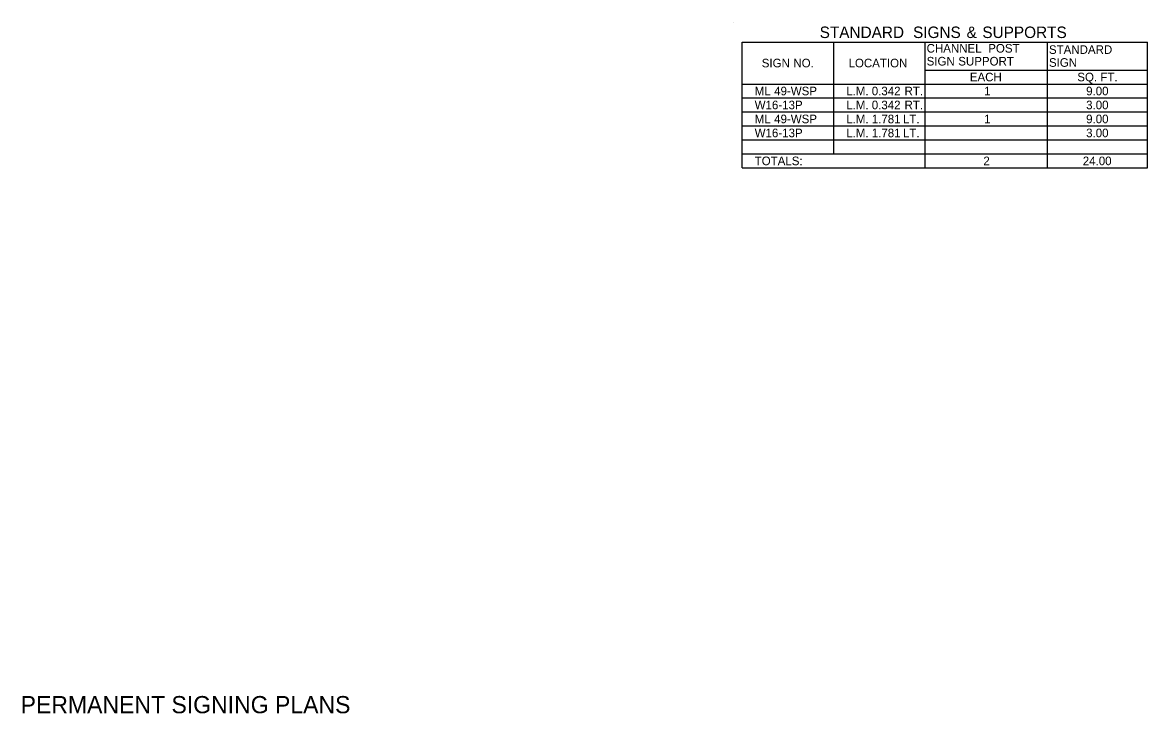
# Model space of a CAD drawing. Extents: x 229 to 4210, y 35 to 1715.
# Drawn here: x 3425 to 4210, y 35 to 517 of the extents above; entities that cross this region are included whole.
import ezdxf

# ---------------------------------------------------------------- set-up
doc = ezdxf.new("R2010")
doc.units = 0
for name, color, linetype in [('B_Steel', 7, 'Continuous'), ('B_Steel Hidden', 7, 'Continuous'), ('Default', 7, 'Continuous')]:
    doc.layers.add(name, color=color, linetype=linetype)

msp = doc.modelspace()

# ---------------------------------------------------------------- linework, layer by layer
at = {"layer": 'B_Steel Hidden'}
msp.add_line((3920.99, 516.95), (3920.99, 516.95), dxfattribs=at)
at = {"layer": 'Default'}
for p, q in [((3926.84, 503.3), (4209.59, 503.3)), ((3926.84, 415.55), (3926.84, 503.3)), ((3926.84, 415.55), (3926.84, 503.3)), ((3990.7, 425.3), (3990.7, 503.3)), ((4054.56, 415.55), (4054.56, 503.3)), ((4139.87, 483.8), (4139.87, 503.3)), ((4139.87, 415.55), (4139.87, 503.3)), ((4209.59, 415.55), (4209.59, 503.3)), ((4054.56, 483.8), (4209.59, 483.8)), ((4054.56, 483.8), (4209.59, 483.8)), ((3926.84, 474.05), (4209.59, 474.05)), ((3990.7, 425.3), (3990.7, 474.05)), ((4054.56, 474.05), (4209.59, 474.05)), ((4054.56, 425.3), (4054.56, 474.05)), ((4139.87, 425.3), (4139.87, 474.05)), ((3926.84, 464.3), (4209.59, 464.3)), ((3926.84, 454.55), (4209.59, 454.55)), ((3926.84, 444.8), (4209.59, 444.8)), ((3926.84, 435.05), (4209.59, 435.05)), ((3926.84, 425.3), (4209.59, 425.3)), ((4209.59, 415.55), (4209.59, 425.3)), ((3926.84, 415.55), (4209.59, 415.55))]:
    msp.add_line(p, q, dxfattribs=at)

# ---------------------------------------------------------------- texts
at = {"layer": 'B_Steel'}
msp.add_text('PERMANENT SIGNING PLANS', height=12, rotation=360, dxfattribs=at).set_placement((3423.61, 35.16))
at = {"layer": 'Default'}
for s, height, p in [('STANDARD', 8, (3980.93, 506.12)), (' SIGNS', 8, (4043.1, 506.12)), (' &', 8, (4080.44, 506.12)), (' SUPPORTS', 8, (4091.44, 506.12)), ('CHANNEL', 6, (4055.54, 495.95)), (' POST', 6, (4096.27, 495.95)), ('STANDARD', 6, (4140.85, 495.05)), ('SIGN', 6, (3940.53, 485.67)), (' NO.', 6, (3960.35, 485.67)), ('LOCATION', 6, (4001.08, 485.67)), ('SIGN', 6, (4055.54, 486.95)), (' SUPPORT', 6, (4075.36, 486.95)), ('SIGN', 6, (4140.85, 486.05)), ('EACH', 6, (4085.66, 475.92)), ('SQ.', 6, (4160.63, 475.92)), (' FT.', 6, (4174.5, 475.92)), ('ML', 6, (3935.61, 466.17)), (' 49-WSP', 6, (3946.96, 466.17)), ('L.M.', 6, (3999.47, 466.17)), (' 0.342', 6, (4015.04, 466.17)), (' RT.', 6, (4037.89, 466.17)), ('1', 6, (4095.66, 466.17)), ('9.00', 6, (4166.78, 466.17)), ('W16-13P', 6, (3935.61, 456.42)), ('L.M.', 6, (3999.47, 456.42)), (' 0.342', 6, (4015.04, 456.42)), (' RT.', 6, (4037.89, 456.42)), ('3.00', 6, (4166.78, 456.42)), ('ML', 6, (3935.61, 446.67)), (' 49-WSP', 6, (3946.96, 446.67)), ('L.M.', 6, (3999.47, 446.67)), (' 1.781', 6, (4015.04, 446.67)), (' LT.', 6, (4036.79, 446.67)), ('1', 6, (4095.66, 446.67)), ('9.00', 6, (4166.78, 446.67)), ('W16-13P', 6, (3935.61, 436.92)), ('L.M.', 6, (3999.47, 436.92)), (' 1.781', 6, (4015.04, 436.92)), (' LT.', 6, (4036.79, 436.92)), ('3.00', 6, (4166.78, 436.92)), ('TOTALS:', 6, (3935.61, 417.42)), ('2', 6, (4095.1, 417.42)), ('24.00', 6, (4164.45, 417.42))]:
    msp.add_text(s, height=height, dxfattribs=at).set_placement(p)

doc.saveas('drawing.dxf')
